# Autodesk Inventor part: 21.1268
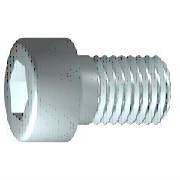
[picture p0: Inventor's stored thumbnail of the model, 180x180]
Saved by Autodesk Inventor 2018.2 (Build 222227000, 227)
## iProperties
Created: 2006-02
Part Number: 21.1268
Material: Steel, Mild
Description: M8X18 SHCS
Document SubType Name: Modeling
Standard: DIN 7984
Designer: Andy Moles
Standards Organization: DIN
Language: en-US
Size Designation: M8 x 20
Categories: <MemberInstance><Categories><Category DisplayName="Fasteners" InternalName="e4da775c-781d-43d5-af7c-5136215cf5a6" Mnemonic="FSTN"><Category DisplayName="Bolts"
Mass: 11.4583 g
Surface Area: 9.67405 cm^2
Volume: 1.45965 cm^3
Density: 7.85 g/cm^3
Vendor: V
Appearance: Zinc
Author: Andy Moles
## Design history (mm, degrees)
sketch "Sketch1"
  geometry: L1 (0.467, 0)-(18, 0); L2 (18, 0)-(18, 4); L3 (18, 4)-(1, 4); L4 (1, 4)-(0.233, 4); L5 (0.233, 4)-(0, 4); L6 (0, 4)-(0, 6.5); L7 (0, 6.5)-(-5, 6.5); L8 (-5, 6.5)-(-5, 2.887); L9 (-5, 2.887)-(-1.2, 2.887); L10 (-1.2, 2.887)-(0.467, 0); L11 (-10, 0)-(25, 0) reference; L12 (0, -1.3)-(0, 7.8) reference; L13 (1, 4)-(0, 4)
  constraints: 22 end point, 6 parallel, 2 collinear, 2 perpendicular, 1 horizontal, 1 point on line
  dimensions: "d1" = 17 distance from line of L3.end L2 (= GEL); "d2" = 0.76691 distance of L4.end L3.end (computed from GAL); "d3" = 5 distance between parallel lines of L8 L6 (= KOH); "d4" = 3.8 distance of L8.end L9.end (= INTI); "d5" = 60 deg angle of L10 L1; "d6" = 8 diameter of L3 L1 (= GD); "d7" = 8 diameter of L5 L1 (= BDM); "d8" = 5.7735 diameter of L9 L1 (= 1.1547 x SW); "d9" = 13 diameter of L7 L1 (= KOD); "d26" = 18 distance between parallel lines of L12 L2 (= NLG)
revolve "Body" sketch "Sketch1" stored, may be unused: angle "d10" = 90 deg
sketch "Sketch2"
  geometry: L1 (0, -9.1)-(0, 9.1) reference; L2 (-9.1, 0)-(9.1, 0) reference; L3 (2.887, 0)-(1.443, -2.5); L4 (1.443, -2.5)-(-1.443, -2.5); L5 (-1.443, -2.5)-(-2.887, 0); L6 (-2.887, 0)-(-1.443, 2.5); L7 (-1.443, 2.5)-(1.443, 2.5); L8 (1.443, 2.5)-(2.887, 0); 2 further points
  constraints: 12 end point, 1 coincident, 1 horizontal alignment, 1 point on line, 12 other
extrude "Slot" join sketch "Sketch2" stored distance "d11" = 10; taper "d12" = 0 deg
workplane "Work Plane1"
body "Solid1"
fillet "Fillet1" dims "d17" = 0.8 (= RR)
feature "Thread" dims "d13" = 18, "d14" = 0
chamfer "Chamfer1" distance "d15" = 0.76681 (= -0.5 x SPD + 0.5 x GD); stored, may be unused: second distance "d16" = 0.76681 (= GUL), angle "d27" = 45 deg
other parameters: "GD" = 8 (= NND) [user parameter; used in 2 equation terms], "NLG" = 18 [user parameter; used in 1 equation term], "GEL" = 17 [user parameter; used in 1 equation term], "KOD" = 13 [user parameter; used in 1 equation term], "KOH" = 5 [user parameter; used in 1 equation term], "INTI" = 3.8 [user parameter; used in 1 equation term], "GAL" = 0.76681 (= 0.61345 x PTC) [user parameter; used in 1 equation term], "GUL" = 0.76681 (= 0.61345 x PTC) [user parameter; used in 1 equation term], "BDM" = 8 (= NND) [user parameter; used in 1 equation term], "SW" = 5 [user parameter; used in 2 equation terms], "RR" = 0.8 [user parameter; used in 1 equation term], "SPD" = 6.46637 (= NND - 1.2269 x PTC) [user parameter; used in 1 equation term], "d19" = 0, "d28" = 0, "d29" = 0, "TOA" = 30 deg [user parameter], "GD1" = 6.46637 (= THREADDIA - 1.2269 x PTC) [user parameter], "THREADDIA" = 8 [user parameter; used in 1 equation term], "FAWI" = 45 deg [user parameter], "ANG" = 120 deg [user parameter], "TPU" = 8 (computed from PTC) [user parameter], "PTC" = 1.25 [user parameter; used in 5 equation terms], "NND" = 8 [user parameter; used in 3 equation terms], "E0" = 5.775 (= 1.155 x SW) [user parameter]
